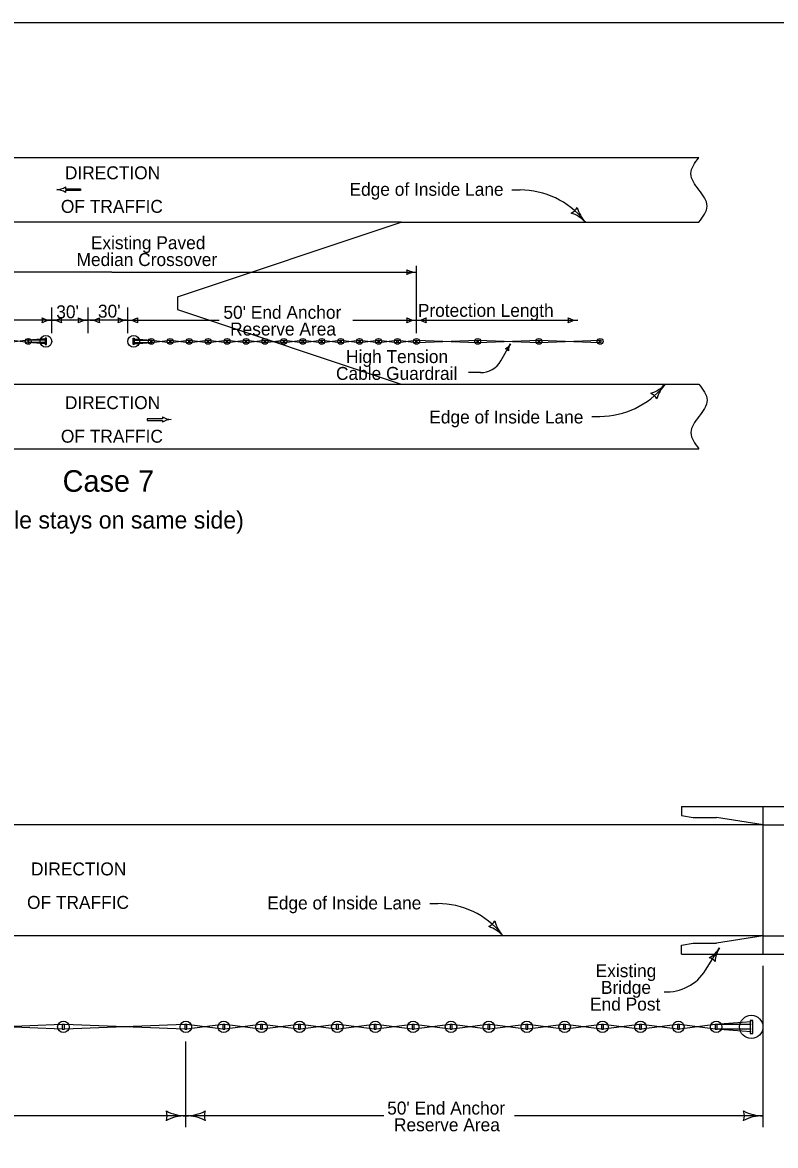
# Model space of a CAD drawing. Extents: x 10133 to 81668, y 7924 to 11018.
# Drawn here: x 14451 to 15149, y 8903 to 9944 of the extents above; entities that cross this region are included whole.
import ezdxf

# ---------------------------------------------------------------- set-up
doc = ezdxf.new("R2010")
doc.units = 0
for name, color, linetype in [('Default', 7, 'Continuous'), ('dsnCellElements', 7, 'Continuous'), ('DsnShtRevisedText', 7, 'Continuous'), ('dsnStdDimension', 7, 'Continuous'), ('Level 8', 7, 'Continuous'), ('SheetBorder', 7, 'Continuous')]:
    doc.layers.add(name, color=color, linetype=linetype)

msp = doc.modelspace()

# ---------------------------------------------------------------- linework, layer by layer
at = {"layer": 'Default'}
for p, q in [((15137.3, 9217.6), (15246.2, 9217.6)), ((15137.3, 9080.5), (15137.3, 9217.6)), ((15137.3, 9200.5), (15235.5, 9200.5)), ((15137.3, 9097.6), (15249.1, 9097.6)), ((15137.3, 9080.5), (15239.3, 9080.5))]:
    msp.add_line(p, q, dxfattribs=at)
at = {"layer": 'dsnCellElements'}
for p, q in [((14456.2, 9649.6), (14439.7, 9647.3)), ((14456.2, 9647.3), (14439.7, 9649.6)), ((14473, 9650.8), (14456.2, 9649.6)), ((14473, 9649.6), (14457.2, 9649.6)), ((14554.3, 9650.8), (14571.1, 9649.6)), ((14554.3, 9649.6), (14570.2, 9649.6)), ((14571.1, 9649.6), (14587.7, 9647.3)), ((14571.1, 9647.3), (14587.7, 9649.6)), ((14588.6, 9649.6), (14605.2, 9647.3)), ((14588.6, 9647.3), (14605.2, 9649.6)), ((14606.2, 9649.6), (14622.8, 9647.3)), ((14606.2, 9647.3), (14622.8, 9649.6)), ((14623.7, 9649.6), (14640.3, 9647.3)), ((14623.7, 9647.3), (14640.3, 9649.6)), ((14641.3, 9649.6), (14657.9, 9647.3)), ((14641.3, 9647.3), (14657.9, 9649.6)), ((14658.8, 9649.6), (14675.5, 9647.3)), ((14658.8, 9647.3), (14675.5, 9649.6)), ((14676.4, 9647.3), (14693, 9649.6)), ((14676.4, 9649.6), (14693, 9647.3)), ((14693.9, 9649.6), (14710.5, 9647.3)), ((14693.9, 9647.3), (14710.5, 9649.6)), ((14711.5, 9649.6), (14728.1, 9647.3)), ((14711.5, 9647.3), (14728.1, 9649.6)), ((14729, 9649.6), (14745.6, 9647.3)), ((14729, 9647.3), (14745.6, 9649.6)), ((14746.6, 9649.6), (14763.2, 9647.3)), ((14746.6, 9647.3), (14763.2, 9649.6)), ((14764.1, 9649.6), (14780.7, 9647.3)), ((14764.1, 9647.3), (14780.7, 9649.6)), ((14781.7, 9649.6), (14798.2, 9647.3)), ((14781.7, 9647.3), (14798.2, 9649.6)), ((14799.2, 9649.6), (14815.8, 9647.3)), ((14799.2, 9647.3), (14815.8, 9649.6)), ((14816.7, 9649.6), (14872.5, 9647.3)), ((14816.7, 9647.3), (14872.5, 9649.6)), ((14873.5, 9649.6), (14929.2, 9647.3)), ((14873.5, 9647.3), (14929.2, 9649.6)), ((14930.2, 9649.6), (14985.9, 9647.3)), ((14930.2, 9647.3), (14985.9, 9649.6)), ((14473, 9646.2), (14456.2, 9647.3)), ((14473, 9647.3), (14457.2, 9647.3)), ((14554.3, 9647.3), (14570.2, 9647.3)), ((14554.3, 9646.2), (14571.1, 9647.3)), ((15061.7, 9217.6), (15137.3, 9217.6)), ((15061.7, 9217.6), (15061.7, 9209.1)), ((15061.7, 9209.1), (15072.5, 9207.3)), ((15072.5, 9207.3), (15094.1, 9207.3)), ((15137.3, 9200.5), (15094.1, 9207.3)), ((15137.3, 9097.6), (15094.1, 9090.9)), ((15137.3, 9080.5), (15137.3, 9097.6)), ((15061.7, 9089.1), (15072.5, 9090.9)), ((15061.7, 9080.5), (15061.7, 9089.1)), ((15072.5, 9090.9), (15094.1, 9090.9)), ((15061.7, 9080.5), (15137.3, 9080.5)), ((14488.2, 9015.5), (14376.7, 9011)), ((14488.2, 9011), (14376.7, 9015.5)), ((14601.6, 9015.5), (14490.1, 9011)), ((14601.6, 9011), (14490.1, 9015.5)), ((14636.8, 9015.5), (14603.5, 9011)), ((14636.8, 9011), (14603.5, 9015.5)), ((14671.8, 9015.5), (14638.6, 9011)), ((14671.8, 9011), (14638.6, 9015.5)), ((14706.9, 9015.5), (14673.7, 9011)), ((14706.9, 9011), (14673.7, 9015.5)), ((14742, 9015.5), (14708.8, 9011)), ((14742, 9011), (14708.8, 9015.5)), ((14777.1, 9015.5), (14743.9, 9011)), ((14777.1, 9011), (14743.9, 9015.5)), ((14812.2, 9015.5), (14779, 9011)), ((14812.2, 9011), (14779, 9015.5)), ((14847.3, 9015.5), (14814, 9011)), ((14847.3, 9011), (14814, 9015.5)), ((14882.3, 9011), (14849.2, 9015.5)), ((14882.3, 9015.5), (14849.2, 9011)), ((14917.5, 9015.5), (14884.2, 9011)), ((14917.5, 9011), (14884.2, 9015.5)), ((14952.5, 9015.5), (14919.4, 9011)), ((14952.5, 9011), (14919.4, 9015.5)), ((14987.7, 9015.5), (14954.4, 9011)), ((14987.7, 9011), (14954.4, 9015.5)), ((15022.7, 9015.5), (14989.6, 9011)), ((15022.7, 9011), (14989.6, 9015.5)), ((15057.9, 9015.5), (15024.6, 9011)), ((15057.9, 9011), (15024.6, 9015.5)), ((15092.9, 9015.5), (15059.8, 9011)), ((15092.9, 9011), (15059.8, 9015.5)), ((15126.4, 9017.8), (15092.9, 9015.5)), ((15126.4, 9015.5), (15094.8, 9015.5)), ((15126.4, 9008.6), (15092.9, 9011)), ((15126.4, 9011), (15094.8, 9011))]:
    msp.add_line(p, q, dxfattribs=at)
for points in [[(14457.2, 9647.3), (14457.2, 9649.6), (14456.2, 9649.6), (14456.2, 9647.3)], [(14473.6, 9645.5), (14473.6, 9651.5), (14472.4, 9651.5), (14472.4, 9645.5)], [(14553.7, 9645.5), (14553.7, 9651.5), (14554.9, 9651.5), (14554.9, 9645.5)], [(14570.2, 9647.3), (14570.2, 9649.6), (14571.1, 9649.6), (14571.1, 9647.3)], [(14587.7, 9647.3), (14587.7, 9649.6), (14588.6, 9649.6), (14588.6, 9647.3)], [(14605.3, 9647.3), (14605.3, 9649.6), (14606.2, 9649.6), (14606.2, 9647.3)], [(14622.8, 9647.3), (14622.8, 9649.6), (14623.7, 9649.6), (14623.7, 9647.3)], [(14640.4, 9647.3), (14640.4, 9649.6), (14641.3, 9649.6), (14641.3, 9647.3)], [(14657.9, 9647.3), (14657.9, 9649.6), (14658.8, 9649.6), (14658.8, 9647.3)], [(14675.5, 9647.3), (14675.5, 9649.6), (14676.4, 9649.6), (14676.4, 9647.3)], [(14693, 9647.3), (14693, 9649.6), (14693.9, 9649.6), (14693.9, 9647.3)], [(14710.5, 9647.3), (14710.5, 9649.6), (14711.5, 9649.6), (14711.5, 9647.3)], [(14728.1, 9647.3), (14728.1, 9649.6), (14729, 9649.6), (14729, 9647.3)], [(14745.6, 9647.3), (14745.6, 9649.6), (14746.6, 9649.6), (14746.6, 9647.3)], [(14763.2, 9647.3), (14763.2, 9649.6), (14764.1, 9649.6), (14764.1, 9647.3)], [(14780.7, 9647.3), (14780.7, 9649.6), (14781.7, 9649.6), (14781.7, 9647.3)], [(14798.2, 9647.3), (14798.2, 9649.6), (14799.2, 9649.6), (14799.2, 9647.3)], [(14815.8, 9647.3), (14815.8, 9649.6), (14816.7, 9649.6), (14816.7, 9647.3)], [(14815.8, 9647.3), (14815.8, 9649.6), (14816.7, 9649.6), (14816.7, 9647.3)], [(14872.5, 9647.3), (14872.5, 9649.6), (14873.5, 9649.6), (14873.5, 9647.3)], [(14872.5, 9647.3), (14872.5, 9649.6), (14873.5, 9649.6), (14873.5, 9647.3)], [(14929.2, 9647.3), (14929.2, 9649.6), (14930.2, 9649.6), (14930.2, 9647.3)], [(14929.2, 9647.3), (14929.2, 9649.6), (14930.2, 9649.6), (14930.2, 9647.3)], [(14985.9, 9647.3), (14985.9, 9649.6), (14986.9, 9649.6), (14986.9, 9647.3)], [(14490.1, 9011), (14490.1, 9015.5), (14488.2, 9015.5), (14488.2, 9011)], [(14490.1, 9011), (14490.1, 9015.5), (14488.2, 9015.5), (14488.2, 9011)], [(14603.5, 9011), (14603.5, 9015.5), (14601.6, 9015.5), (14601.6, 9011)], [(14603.5, 9011), (14603.5, 9015.5), (14601.6, 9015.5), (14601.6, 9011)], [(14638.6, 9011), (14638.6, 9015.5), (14636.8, 9015.5), (14636.8, 9011)], [(14673.7, 9011), (14673.7, 9015.5), (14671.8, 9015.5), (14671.8, 9011)], [(14708.8, 9011), (14708.8, 9015.5), (14706.9, 9015.5), (14706.9, 9011)], [(14743.9, 9011), (14743.9, 9015.5), (14742, 9015.5), (14742, 9011)], [(14779, 9011), (14779, 9015.5), (14777.1, 9015.5), (14777.1, 9011)], [(14814, 9011), (14814, 9015.5), (14812.2, 9015.5), (14812.2, 9011)], [(14849.2, 9011), (14849.2, 9015.5), (14847.3, 9015.5), (14847.3, 9011)], [(14884.2, 9011), (14884.2, 9015.5), (14882.3, 9015.5), (14882.3, 9011)], [(14919.4, 9011), (14919.4, 9015.5), (14917.5, 9015.5), (14917.5, 9011)], [(14954.4, 9011), (14954.4, 9015.5), (14952.5, 9015.5), (14952.5, 9011)], [(14989.6, 9011), (14989.6, 9015.5), (14987.7, 9015.5), (14987.7, 9011)], [(15024.6, 9011), (15024.6, 9015.5), (15022.7, 9015.5), (15022.7, 9011)], [(15059.8, 9011), (15059.8, 9015.5), (15057.9, 9015.5), (15057.9, 9011)], [(15094.8, 9011), (15094.8, 9015.5), (15092.9, 9015.5), (15092.9, 9011)], [(15127.7, 9007.2), (15127.7, 9019.2), (15125.2, 9019.2), (15125.2, 9007.2)]]:
    msp.add_lwpolyline(points, close=True, dxfattribs=at)
for centre, radius in [((14456.7, 9648.5), 2.66), ((14473, 9648.5), 5.4), ((14554.3, 9648.5), 5.4), ((14570.6, 9648.5), 2.66), ((14588.1, 9648.5), 2.66), ((14605.7, 9648.5), 2.66), ((14623.2, 9648.5), 2.66), ((14640.8, 9648.5), 2.66), ((14658.4, 9648.5), 2.66), ((14675.9, 9648.5), 2.66), ((14693.4, 9648.5), 2.66), ((14711, 9648.5), 2.66), ((14728.5, 9648.5), 2.66), ((14746.1, 9648.5), 2.66), ((14763.6, 9648.5), 2.66), ((14781.2, 9648.5), 2.66), ((14798.7, 9648.5), 2.66), ((14816.3, 9648.5), 2.66), ((14816.3, 9648.5), 2.66), ((14873, 9648.5), 2.66), ((14873, 9648.5), 2.66), ((14929.7, 9648.5), 2.66), ((14929.7, 9648.5), 2.66), ((14986.4, 9648.5), 2.66), ((15126.4, 9013.2), 10.8), ((14489.2, 9013.2), 5.32), ((14489.2, 9013.2), 5.32), ((14602.6, 9013.2), 5.32), ((14602.6, 9013.2), 5.32), ((14637.7, 9013.2), 5.32), ((14672.7, 9013.2), 5.32), ((14707.9, 9013.2), 5.32), ((14742.9, 9013.2), 5.32), ((14778.1, 9013.2), 5.32), ((14813.1, 9013.2), 5.32), ((14848.2, 9013.2), 5.32), ((14883.3, 9013.2), 5.32), ((14918.4, 9013.2), 5.32), ((14953.5, 9013.2), 5.32), ((14988.6, 9013.2), 5.32), ((15023.7, 9013.2), 5.32), ((15058.8, 9013.2), 5.32), ((15093.9, 9013.2), 5.32)]:
    msp.add_circle(centre, radius, dxfattribs=at)
at = {"layer": 'DsnShtRevisedText'}
for p, q in [((14483, 9789.1), (14483, 9789.1)), ((14491.1, 9791.6), (14491.1, 9789.8)), ((14491.1, 9789.8), (14505, 9789.8)), ((14505, 9788.3), (14491.1, 9788.3)), ((14491.1, 9788.3), (14491.1, 9786.5)), ((14505, 9789.8), (14505, 9788.3)), ((14904.7, 9788.8), (14912.2, 9788.8)), ((14534, 9712.6), (14211.1, 9712.6)), ((14534, 9712.6), (14816.3, 9712.6)), ((14816.3, 9656), (14816.3, 9718.6)), ((14478.4, 9656), (14478.4, 9680)), ((14512, 9656), (14512, 9680)), ((14548.9, 9656), (14548.9, 9680)), ((14478.4, 9668), (14393.7, 9668)), ((14548.9, 9668), (14478.4, 9668)), ((14548.9, 9668), (14633.4, 9668)), ((14757.2, 9668), (14816.3, 9668)), ((14816.3, 9668), (14838.7, 9668)), ((14838.7, 9668), (14965.7, 9668)), ((14894.3, 9630.5), (14903.2, 9646.1)), ((14875.5, 9619.7), (14864.3, 9619.7)), ((14580.9, 9576.8), (14566.9, 9576.8)), ((14566.9, 9576.8), (14566.9, 9575.3)), ((14566.9, 9575.3), (14580.9, 9575.3)), ((14580.9, 9578.6), (14580.9, 9576.8)), ((14580.9, 9575.3), (14580.9, 9573.5)), ((14589, 9576.1), (14589, 9576.1)), ((14978.6, 9579), (14986.1, 9579)), ((14828.5, 9127.5), (14835.9, 9127.5)), ((15084.1, 9065.7), (15097, 9086.4)), ((15137.3, 8920.3), (15137.3, 9069.8)), ((14602.6, 8920.3), (14602.6, 8999.6)), ((14559.7, 8930.8), (14391.7, 8930.8)), ((14786.1, 8930.8), (14559.7, 8930.8)), ((15137.3, 8930.8), (14907.1, 8930.8))]:
    msp.add_line(p, q, dxfattribs=at)
for centre, radius, start, end in [((14482.3, 9805.4), 16.4, 272.352, 302.382), ((14482.3, 9772.7), 16.4, 57.618, 87.648), ((14912.2, 9712.6), 76.2, 39.0106, 90), ((14954.2, 9778.7), 12.5, 295.2639, 330.7306), ((14949, 9736.8), 32.4, 42.9973, 71.0698), ((14996.4, 9781), 32.4, 194.9248, 222.9973), ((14800.2, 9712.6), 7.39, 342.2666, 17.7333), ((14816.3, 9731.7), 19.1, 241.9275, 270), ((14816.3, 9693.5), 19.1, 90, 118.0725), ((14462.4, 9668), 7.39, 342.2666, 17.7333), ((14478.4, 9687.1), 19.1, 241.9275, 270), ((14478.4, 9687.1), 19.1, 270, 298.0725), ((14494.4, 9668), 7.39, 162.2666, 197.7334), ((14496, 9668), 7.39, 342.2666, 17.7333), ((14512, 9687.1), 19.1, 241.9275, 270), ((14513.7, 9687.1), 19.1, 270, 298.0725), ((14529.7, 9668), 7.39, 162.2666, 197.7334), ((14532.9, 9668), 7.39, 342.2666, 17.7333), ((14548.9, 9687.1), 19.1, 241.9275, 270), ((14548.9, 9687.1), 19.1, 270, 298.0725), ((14565, 9668), 7.39, 162.2666, 197.7334), ((14800.2, 9668), 7.39, 342.2666, 17.7333), ((14816.3, 9687.1), 19.1, 241.9275, 270), ((14816.3, 9687.1), 19.1, 270, 298.0725), ((14832.3, 9668), 7.39, 162.2666, 197.7334), ((14949.6, 9668), 7.39, 342.2666, 17.7333), ((14965.7, 9687.1), 19.1, 241.9275, 270), ((14478.4, 9648.9), 19.1, 90, 118.0725), ((14478.4, 9648.9), 19.1, 61.9275, 90), ((14512, 9648.9), 19.1, 90, 118.0725), ((14513.7, 9648.9), 19.1, 61.9275, 90), ((14548.9, 9648.9), 19.1, 90, 118.0725), ((14548.9, 9648.9), 19.1, 61.9275, 90), ((14816.3, 9648.9), 19.1, 90, 118.0725), ((14816.3, 9648.9), 19.1, 61.9275, 90), ((14965.7, 9648.9), 19.1, 90, 118.0725), ((14891.5, 9653), 13.6, 301.6962, 329.7686), ((14897.5, 9636.3), 5.25, 42.0353, 77.502), ((14915, 9639.3), 13.6, 149.7686, 177.8411), ((14875.5, 9641.4), 21.8, 270, 329.7757), ((14986.1, 9655.2), 76.2, 270, 320.9894), ((15022.9, 9631), 32.4, 288.9302, 317.0027), ((15070.3, 9586.8), 32.4, 137.0027, 165.0752), ((15028.1, 9589), 12.5, 29.2694, 64.7361), ((14589.7, 9592.4), 16.4, 237.618, 267.648), ((14589.7, 9559.7), 16.4, 92.352, 122.382), ((14835.9, 9051.3), 76.2, 39.0106, 90), ((14877.9, 9117.5), 12.5, 295.2639, 330.7306), ((14920.1, 9119.7), 32.4, 194.9248, 222.9973), ((14872.7, 9075.5), 32.4, 42.9973, 71.0698), ((15074.1, 9101), 27.2, 299.3484, 327.4209), ((15119.9, 9071.8), 27.2, 147.4209, 175.4934), ((15084.7, 9067.2), 10.5, 39.6875, 75.1542), ((15047.4, 9089.1), 43.5, 267.6522, 327.4279), ((14570.5, 8930.8), 14.8, 342.2666, 17.7333), ((14602.6, 8969.1), 38.3, 241.9275, 270), ((14602.6, 8892.6), 38.3, 90, 118.0725), ((14602.6, 8969.1), 38.3, 270, 298.0725), ((14602.6, 8892.6), 38.3, 61.9275, 90), ((14634.6, 8930.8), 14.8, 162.2666, 197.7334), ((15105.2, 8930.8), 14.8, 342.2666, 17.7333), ((15137.3, 8969.1), 38.3, 241.9275, 270), ((15137.3, 8892.6), 38.3, 90, 118.0725)]:
    msp.add_arc(centre, radius, start, end, dxfattribs=at)
at = {"layer": 'dsnStdDimension'}
for p, q in [((13962.2, 9818.9), (15077.9, 9818.9)), ((14802, 9758.9), (14238, 9758.9)), ((14595, 9689.9), (14802, 9758.9)), ((14798.9, 9758.9), (15077.9, 9758.9)), ((14595, 9689.9), (14595, 9677.9)), ((14595, 9677.9), (14802, 9608.9)), ((14241.1, 9608.9), (14802, 9608.9)), ((14802, 9608.9), (15077.9, 9608.9)), ((13962.2, 9548.9), (15077.9, 9548.9)), ((15137.3, 9200.5), (13916.8, 9200.5)), ((15137.3, 9097.6), (13916.8, 9097.6))]:
    msp.add_line(p, q, dxfattribs=at)
for points in [[(15077.9, 9758.9), (15085.4, 9773.9), (15077.9, 9788.9), (15070.4, 9803.9), (15077.9, 9818.9)], [(15077.9, 9608.9), (15085.4, 9593.9), (15077.9, 9578.9), (15070.4, 9563.9), (15077.9, 9548.9)]]:
    msp.add_spline(points, degree=3, dxfattribs=at)
at = {"layer": 'SheetBorder'}
msp.add_lwpolyline([(13732.5, 9944), (16867.5, 9944), (16867.5, 7924), (13732.5, 7924)], close=True, dxfattribs=at)

# ---------------------------------------------------------------- texts
at = {"layer": 'DsnShtRevisedText'}
for s, p in [('DIRECTION', (14490.6, 9798.7)), ('Edge of Inside Lane', (14754.2, 9783.4)), ('OF TRAFFIC', (14486.9, 9767.6)), ('Existing Paved', (14514.6, 9733.9)), ('Median Crossover', (14501.4, 9718.3)), ("30'", (14482.6, 9669.9)), ("30'", (14521.2, 9670.5)), ("50' End Anchor", (14637.4, 9669.4)), ('Protection Length', (14817.5, 9671.2)), ('Reserve Area', (14643.6, 9653.9)), ('High Tension', (14751, 9628.4)), ('Cable Guardrail', (14741.7, 9612.8)), ('DIRECTION', (14490.6, 9585.7)), ('Edge of Inside Lane', (14828.1, 9572.4)), ('OF TRAFFIC', (14486.9, 9554.6)), ('DIRECTION', (14459.2, 9153.6)), ('OF TRAFFIC', (14455.5, 9122.6)), ('Edge of Inside Lane', (14678, 9122.1)), ('Existing', (14982.2, 9059.3)), ('Bridge', (14987.1, 9043.8)), ('End Post', (14977, 9028.3)), ("50' End Anchor", (14789.1, 8932)), ('Reserve Area', (14795.4, 8916.5))]:
    msp.add_text(s, height=12, dxfattribs=at).set_placement(p)
at = {"layer": 'Level 8'}
for s, height, p in [('Case 7', 20, (14488.5, 9509.1)), ('(Cable stays on same side)', 16, (14397.1, 9475))]:
    msp.add_text(s, height=height, dxfattribs=at).set_placement(p)

doc.saveas('drawing.dxf')
